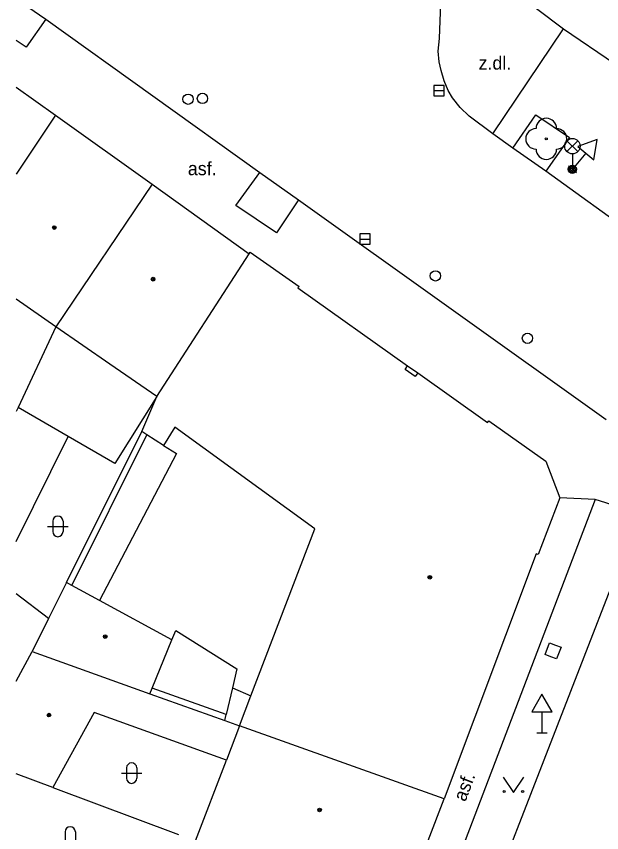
# Model space of a CAD drawing. Extents: x -596229 to -595156, y -1161237 to -1159376.
# Drawn here: x -596228.22 to -596199.72, y -1161042.27 to -1161002.54 of the extents above; entities that cross this region are included whole.
import ezdxf

# ---------------------------------------------------------------- set-up
doc = ezdxf.new("R2010")
doc.units = 0
for name, color, linetype in [('DOP - kresba z DSPS bez souradnic', 7, 'Continuous'), ('DOP - ploty', 7, 'Continuous'), ('DOP - rozhrani ploch obecne', 7, 'Continuous'), ('Level 22', 7, 'Continuous'), ('Level 27', 7, 'Continuous'), ('Level 28', 7, 'Continuous'), ('Level 33', 7, 'Continuous'), ('Level 34', 7, 'Continuous'), ('Level 36', 7, 'Continuous'), ('Level 39', 7, 'Continuous'), ('plynovod - povrch.  znaky - PRIS skut. velikost', 7, 'Continuous'), ('slaboproud - povrch.  znaky a tel. budka skut. velikost', 7, 'Continuous'), ('Specificka linie pasportu komunikaci', 7, 'Continuous'), ('TM - budovy zdene_ betonove - VP', 7, 'Continuous'), ('TM - chodniky - VP', 7, 'Continuous'), ('TM - komunikace - VP', 7, 'Continuous'), ('TM - letecke snimky - pomocna linie', 7, 'Continuous'), ('TM - popis povrchu', 7, 'Continuous'), ('TM - rozhrani mezi zpev. plochami mezi sebou - VP', 7, 'Continuous'), ('TM - rozhrani ploch obecne - VP', 7, 'Continuous')]:
    doc.layers.add(name, color=color, linetype=linetype)

msp = doc.modelspace()

# ---------------------------------------------------------------- linework, layer by layer
at = {"layer": 'DOP - kresba z DSPS bez souradnic'}
for points in [[(-596225.51, -1161030.24), (-596221.86, -1161022.91)], [(-596221.05, -1161023.42), (-596220.43, -1161023.81)], [(-596220.43, -1161023.81), (-596224.17, -1161030.97)], [(-596226.65, -1161031.85), (-596228.22, -1161030.652)], [(-596220.65, -1161032.89), (-596220.46, -1161032.44)], [(-596220.46, -1161032.44), (-596217.48, -1161034.3)], [(-596217.48, -1161034.3), (-596217.69, -1161035.23)], [(-596218, -1161036.52), (-596221.61, -1161035.24)], [(-596217.69, -1161035.23), (-596218, -1161036.52)], [(-596217.69, -1161035.23), (-596216.8, -1161035.62)], [(-596218.07, -1161036.82), (-596218, -1161036.52)]]:
    msp.add_lwpolyline(points, dxfattribs=at)
at = {"layer": 'DOP - ploty'}
for points in [[(-596226.29, -1161017.65), (-596228.13, -1161021.58)], [(-596228.13, -1161021.58), (-596228.22, -1161021.769)]]:
    msp.add_lwpolyline(points, dxfattribs=at)
at = {"layer": 'DOP - rozhrani ploch obecne'}
for points in [[(-596225.77, -1161030.1), (-596222.11, -1161022.75)], [(-596226.44, -1161040.08), (-596220.33, -1161042.36)]]:
    msp.add_lwpolyline(points, dxfattribs=at)
at = {"layer": 'Level 22'}
msp.add_circle((-596202.42, -1161008.5), 0.05, dxfattribs=at)
for centre, start, end in [((-596202.42, -1161008), 0, 180), ((-596202.92, -1161008.5), 90, 270), ((-596201.92, -1161008.5), 270, 90), ((-596202.42, -1161009), 180, 0)]:
    msp.add_arc(centre, 0.5, start, end, dxfattribs=at)
at = {"layer": 'Level 27'}
for p, q in [((-596207.9, -1161006.15), (-596207.4, -1161006.15)), ((-596211.5, -1161013.38), (-596211, -1161013.38))]:
    msp.add_line(p, q, dxfattribs=at)
for points in [[(-596207.9, -1161006.4), (-596207.4, -1161006.4), (-596207.4, -1161005.9), (-596207.9, -1161005.9)], [(-596211.5, -1161013.63), (-596211, -1161013.63), (-596211, -1161013.13), (-596211.5, -1161013.13)]]:
    msp.add_lwpolyline(points, close=True, dxfattribs=at)
at = {"layer": 'Level 28'}
for centre in [(-596219.86, -1161006.57), (-596219.16, -1161006.53), (-596207.82, -1161015.17), (-596203.34, -1161018.21)]:
    msp.add_circle(centre, 0.25, dxfattribs=at)
at = {"layer": 'Level 33'}
for p, q in [((-596201.415, -1161009.12), (-596200.885, -1161008.59)), ((-596201.415, -1161008.59), (-596200.885, -1161009.12)), ((-596201.15, -1161009.23), (-596201.15, -1161009.98))]:
    msp.add_line(p, q, dxfattribs=at)
for centre, radius in [((-596201.15, -1161008.855), 0.375), ((-596201.15, -1161009.98), 0.2), ((-596201.15, -1161009.98), 0.145), ((-596201.15, -1161009.98), 0.0876)]:
    msp.add_circle(centre, radius, dxfattribs=at)
at = {"layer": 'Level 34'}
for p, q in [((-596200.496, -1161009.2), (-596201.15, -1161009.98)), ((-596201.342, -1161009.819), (-596200.958, -1161010.141)), ((-596202.63, -1161036.392), (-596202.63, -1161037.41)), ((-596202.88, -1161037.41), (-596202.38, -1161037.41))]:
    msp.add_line(p, q, dxfattribs=at)
for points in [[(-596200.879, -1161008.879), (-596200.113, -1161009.522), (-596199.939, -1161008.537)], [(-596203.13, -1161036.392), (-596202.13, -1161036.392), (-596202.63, -1161035.526)]]:
    msp.add_lwpolyline(points, close=True, dxfattribs=at)
at = {"layer": 'Level 36'}
for p, q in [((-596226.446, -1161027.116), (-596226.446, -1161027.616)), ((-596225.946, -1161027.116), (-596225.946, -1161027.616)), ((-596226.696, -1161027.366), (-596225.696, -1161027.366)), ((-596223.106, -1161039.376), (-596222.106, -1161039.376)), ((-596222.856, -1161039.126), (-596222.856, -1161039.626)), ((-596222.356, -1161039.126), (-596222.356, -1161039.626)), ((-596225.846, -1161042.236), (-596225.846, -1161042.736)), ((-596225.346, -1161042.236), (-596225.346, -1161042.736))]:
    msp.add_line(p, q, dxfattribs=at)
msp.add_lwpolyline([(-596204.52, -1161039.57), (-596204.02, -1161040.32), (-596203.52, -1161039.57)], dxfattribs=at)
for centre in [(-596204.47, -1161040.27), (-596203.571, -1161040.27)]:
    msp.add_circle(centre, 0.05, dxfattribs=at)
for centre, start, end in [((-596226.196, -1161027.116), 0, 180), ((-596226.196, -1161027.616), 180, 0), ((-596222.606, -1161039.126), 0, 180), ((-596222.606, -1161039.626), 180, 0), ((-596225.596, -1161042.236), 0, 180)]:
    msp.add_arc(centre, 0.25, start, end, dxfattribs=at)
at = {"layer": 'Level 39'}
for centre, radius in [((-596226.37, -1161012.82), 0.09), ((-596226.37, -1161012.82), 0.0398), ((-596221.56, -1161015.33), 0.09), ((-596221.56, -1161015.33), 0.0398), ((-596208.09, -1161029.84), 0.09), ((-596208.09, -1161029.84), 0.0398), ((-596223.89, -1161032.73), 0.09), ((-596223.89, -1161032.73), 0.0398), ((-596226.63, -1161036.55), 0.09), ((-596226.63, -1161036.55), 0.0398), ((-596213.46, -1161041.17), 0.09), ((-596213.46, -1161041.17), 0.0398)]:
    msp.add_circle(centre, radius, dxfattribs=at)
at = {"layer": 'plynovod - povrch.  znaky - PRIS skut. velikost'}
msp.add_lwpolyline([(-596208.68, -1161019.89), (-596208.8, -1161020.07), (-596209.29, -1161019.72), (-596209.17, -1161019.55)], dxfattribs=at)
at = {"layer": 'slaboproud - povrch.  znaky a tel. budka skut. velikost'}
for points in [[(-596202.2, -1161033.71), (-596202.48, -1161033.6), (-596202.26, -1161033.04)], [(-596202.26, -1161033.04), (-596201.98, -1161033.15)], [(-596201.98, -1161033.15), (-596201.7, -1161033.25), (-596201.92, -1161033.81), (-596202.2, -1161033.71)]]:
    msp.add_lwpolyline(points, dxfattribs=at)
at = {"layer": 'Specificka linie pasportu komunikaci'}
msp.add_lwpolyline([(-596200.04, -1161026.05), (-596201.76, -1161025.98)], dxfattribs=at)
at = {"layer": 'TM - budovy zdene_ betonove - VP'}
for points in [[(-596202.89, -1161002.15), (-596201.59, -1161003.15)], [(-596201.59, -1161003.15), (-596196.62, -1161006.52)], [(-596228.22, -1161005.981), (-596226.31, -1161007.35)], [(-596226.31, -1161007.35), (-596228.22, -1161010.212)], [(-596226.31, -1161007.35), (-596221.61, -1161010.71)], [(-596221.61, -1161010.71), (-596226.29, -1161017.65)], [(-596221.61, -1161010.71), (-596216.88, -1161014.09)], [(-596216.88, -1161014.09), (-596216.83, -1161014.01)], [(-596216.83, -1161014.01), (-596214.45, -1161015.68)], [(-596221.38, -1161021.04), (-596216.88, -1161014.09)], [(-596214.45, -1161015.68), (-596214.51, -1161015.76)], [(-596214.51, -1161015.76), (-596209.17, -1161019.55)], [(-596226.29, -1161017.65), (-596228.22, -1161016.308)], [(-596223.66, -1161019.46), (-596226.29, -1161017.65)], [(-596221.38, -1161021.04), (-596223.66, -1161019.46)], [(-596209.17, -1161019.55), (-596208.68, -1161019.89)], [(-596208.68, -1161019.89), (-596205.28, -1161022.3)], [(-596222.11, -1161022.75), (-596221.38, -1161021.04)], [(-596205.28, -1161022.3), (-596205.22, -1161022.22)], [(-596205.22, -1161022.22), (-596202.44, -1161024.19)], [(-596221.86, -1161022.91), (-596222.11, -1161022.75)], [(-596220.5, -1161022.54), (-596221.05, -1161023.42)], [(-596213.69, -1161027.48), (-596220.5, -1161022.54)], [(-596221.05, -1161023.42), (-596221.86, -1161022.91)], [(-596202.44, -1161024.19), (-596201.76, -1161025.98)], [(-596201.76, -1161025.98), (-596202.82, -1161028.74)], [(-596216.8, -1161035.62), (-596213.69, -1161027.48)], [(-596202.91, -1161028.7), (-596207.4, -1161040.63)], [(-596202.82, -1161028.74), (-596202.91, -1161028.7)], [(-596225.77, -1161030.1), (-596226.65, -1161031.85)], [(-596225.51, -1161030.24), (-596225.77, -1161030.1)], [(-596224.17, -1161030.97), (-596225.51, -1161030.24)], [(-596220.65, -1161032.89), (-596224.17, -1161030.97)], [(-596226.65, -1161031.85), (-596227.45, -1161033.46)], [(-596221.61, -1161035.24), (-596220.65, -1161032.89)], [(-596228.22, -1161034.896), (-596227.45, -1161033.46)], [(-596227.45, -1161033.46), (-596221.72, -1161035.51)], [(-596221.72, -1161035.51), (-596221.61, -1161035.24)], [(-596221.72, -1161035.51), (-596218.07, -1161036.82)], [(-596217.35, -1161037.07), (-596216.8, -1161035.62)], [(-596224.43, -1161036.43), (-596226.44, -1161040.08)], [(-596217.99, -1161038.74), (-596224.43, -1161036.43)], [(-596218.07, -1161036.82), (-596217.35, -1161037.07)], [(-596217.35, -1161037.07), (-596217.99, -1161038.74)], [(-596207.4, -1161040.63), (-596217.35, -1161037.07)], [(-596219.49, -1161042.67), (-596217.99, -1161038.74)], [(-596226.44, -1161040.08), (-596228.22, -1161039.406)], [(-596209.56, -1161046.29), (-596207.4, -1161040.63)]]:
    msp.add_lwpolyline(points, dxfattribs=at)
at = {"layer": 'TM - chodniky - VP'}
for points in [[(-596226.79, -1161002.68), (-596227.74, -1161004.04), (-596228.22, -1161003.704)], [(-596204.05, -1161008.95), (-596202.93, -1161007.33), (-596201.29, -1161008.43), (-596202.45, -1161010.07)], [(-596200.04, -1161026.05), (-596207.88, -1161046.61), (-596205.88, -1161047.38)], [(-596197.87, -1161026.73), (-596200.04, -1161026.05)]]:
    msp.add_lwpolyline(points, dxfattribs=at)
at = {"layer": 'TM - komunikace - VP'}
for points in [[(-596228.22, -1161001.664), (-596226.79, -1161002.68)], [(-596207.62, -1161003.61), (-596207.53, -1161001.48)], [(-596226.79, -1161002.68), (-596216.36, -1161010.13)], [(-596206.17, -1161007.4), (-596206.61, -1161006.98), (-596206.99, -1161006.51), (-596207.19, -1161006.15), (-596207.4, -1161005.68), (-596207.54, -1161005.18), (-596207.64, -1161004.75), (-596207.68, -1161004.23), (-596207.62, -1161003.61)], [(-596205.02, -1161008.25), (-596206.17, -1161007.4)], [(-596204.05, -1161008.95), (-596205.02, -1161008.25)], [(-596202.45, -1161010.07), (-596204.05, -1161008.95)], [(-596216.36, -1161010.13), (-596214.48, -1161011.47)], [(-596197.94, -1161013.31), (-596202.45, -1161010.07)], [(-596214.48, -1161011.47), (-596199.51, -1161022.16)], [(-596205.88, -1161047.38), (-596197.87, -1161026.73)]]:
    msp.add_lwpolyline(points, dxfattribs=at)
at = {"layer": 'TM - letecke snimky - pomocna linie'}
for points in [[(-596221.38, -1161021.04), (-596223.42, -1161024.3), (-596225.69, -1161022.99)], [(-596225.69, -1161022.99), (-596228.13, -1161021.58)], [(-596228.22, -1161028.099), (-596225.69, -1161022.99)]]:
    msp.add_lwpolyline(points, dxfattribs=at)
at = {"layer": 'TM - rozhrani mezi zpev. plochami mezi sebou - VP'}
msp.add_lwpolyline([(-596205.02, -1161008.25), (-596201.59, -1161003.15)], dxfattribs=at)
at = {"layer": 'TM - rozhrani ploch obecne - VP'}
msp.add_lwpolyline([(-596214.48, -1161011.47), (-596215.56, -1161013.07), (-596217.54, -1161011.75), (-596216.36, -1161010.13)], dxfattribs=at)

# ---------------------------------------------------------------- texts
at = {"layer": 'TM - popis povrchu'}
for s, p in [('z.dl.', (-596205.72, -1161005.13)), ('asf.', (-596219.87, -1161010.27))]:
    msp.add_text(s, height=0.65, dxfattribs=at).set_placement(p)
msp.add_text('asf.', height=0.65, rotation=69.11, dxfattribs=at).set_placement((-596206.36, -1161040.8))

doc.saveas('drawing.dxf')
